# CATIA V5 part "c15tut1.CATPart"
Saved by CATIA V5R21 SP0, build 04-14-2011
Part number: Part1
Bounding box of the stored display mesh (mm): x -21 to 122, y 0 to 45, z -43 to 1
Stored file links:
  D:\CATIA V5R21 E-RESOURCES\CATIA-V5R21\catia-v5r21-prt\c15-catia-v5r20-prt\c15-catia-v5r21-tut01.CATPart
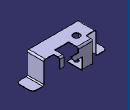
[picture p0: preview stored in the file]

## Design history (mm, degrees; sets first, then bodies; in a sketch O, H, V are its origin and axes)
SheetMetalParameters1: Thickness 1, BendRadius 2, KFactor 0.400515 {= log(min(100,max(20*SheetMetalParameters1.BendRadius,SheetMetalParameters1.Thickness)/SheetMetalParameters1.Thickness))/log(100)/2}, ReliefRadialLength 1, ReliefAxialLength 2, MinimumBendRadius 0
Body1 (main body)
  Sketch1 on xy-plane, origin (0, 0, 0), H (1, 0, 0), V (0, 1, 0)
    line L1 (0, 0) -> (101, 0)
    line L2 (101, 0) -> (101, 32)
    line L3 (101, 32) -> (82, 32)
    line L4 (82, 32) -> (82, 44)
    line L5 (82, 44) -> (74, 44)
    line L6 (74, 44) -> (74, 26)
    line L7 (74, 26) -> (47, 26)
    line L8 (47, 26) -> (47, 44)
    point P8 (47, 44)
    line L9 (47, 44) -> (20, 44)
    line L10 (20, 44) -> (20, 32)
    point P10 (20, 32)
    line L11 (20, 32) -> (0, 32)
    point P11 (0, 32)
    line L12 (0, 32) -> (0, 0)
    length L1 = 101
    length L2 = 32
    length L3 = 19
    length L5 = 8
    distance L1 L5 = 44
    distance L7 L1 = 26
    length L11 = 20
    length L9 = 27
    horizontal: L1 H, L3 H, L5 H, L7 H, L9 H, L11 H
    vertical: L2 V, L4 V, L6 V, L8 V, L10 V, L12 V
    coincidence: P8 L5, P10 L3, P11 V
  Wall1: Thickness 1, Profile Sketch1
  Flange1: Angle 90, Length 44, Radius 2, KFacteur 0.400515 {= log(min(100,max(20*Flange1.Radius,SheetMetalParameters1.Thickness)/SheetMetalParameters1.Thickness))/log(100)/2}, Guide edge [face of Wall1 | face of Wall1]
  Flange2: Angle 90, Length 44, Radius 2, KFacteur 0.400515 {= log(min(100,max(20*Flange2.Radius,SheetMetalParameters1.Thickness)/SheetMetalParameters1.Thickness))/log(100)/2}, Guide edge [face of Wall1 | face of Wall1]
  Flange3: Angle 90, Length 22, Radius 2, KFacteur 0.400515 {= log(min(100,max(20*Flange3.Radius,SheetMetalParameters1.Thickness)/SheetMetalParameters1.Thickness))/log(100)/2}, Guide edge [face of Flange2 | face of Flange2]
  Flange4: Angle 90, Length 22, Radius 2, KFacteur 0.400515 {= log(min(100,max(20*Flange4.Radius,SheetMetalParameters1.Thickness)/SheetMetalParameters1.Thickness))/log(100)/2}, Guide edge [face of Flange1 | face of Flange1]
  Sketch2 on face of Wall1, origin (47, 44, 0), H (-1, 0, 0), V (0, 0, 1)
    point P1 (0, 1)
    line L1 (0, 1) -> (0, -8)
    line L2 (0, -8) -> (-13, -8)
    line L3 (-13, -8) -> (-13, -18)
    line L4 (-13, -18) -> (8, -18)
    line L5 (8, -18) -> (8, -42)
    line L6 (8, -42) -> (27, -42)
    line L7 (27, -42) -> (27, 1)
    line L8 (27, 1) -> (0, 1)
    reference projected line E1 (27, 0) -> (27, 1) from edge [face of Wall1 | face of Wall1]
    reference projected line E2 (0, 1) -> (27, 1) from edge [face of Wall1 | face of Wall1]
    length L6 = 19
    length L7 = 43
    length L3 = 10
    distance L4 L8 = 19
    distance L3 L7 = 40
    coincidence: P1 V, L7 E1, L8 E2
    horizontal: L2 H, L4 H, L6 H
    vertical: L3 V, L5 V, L7 V, L1 V
  d_NewWallOnEdge1: NewWallOnEdge_Edge edge [face of Wall1 | face of Wall1], NewWallOnEdge_WallProfile Sketch2, NewWallOnEdge_Length 27, NewWallOnEdge_HeightLimitOffset 0, NewWallOnEdge_WidthOffset1 0, NewWallOnEdge_WidthOffset2 0, NewWallOnEdge_Angle 0, NewWallOnEdge_BendRadiusValue 2 {= SheetMetalParameters1.BendRadius}, NewWallOnEdge_BendTable SheetMetalParameters1, KFacteur 0.400515 {= log(min(100,max(20*d_NewWallOnEdge1.Radius,SheetMetalParameters1.Thickness)/SheetMetalParameters1.Thickness))/log(100)/2}
  Flange5: Angle 90, Length 19, Radius 2, KFacteur 0.400515 {= log(min(100,max(20*Flange5.Radius,SheetMetalParameters1.Thickness)/SheetMetalParameters1.Thickness))/log(100)/2}, Guide edge [face of Wall1 | face of Wall1]
  Flange6: Angle 90, Length 30, Radius 2, KFacteur 0.400515 {= log(min(100,max(20*Flange6.Radius,SheetMetalParameters1.Thickness)/SheetMetalParameters1.Thickness))/log(100)/2}, Guide edge [face of d_NewWallOnEdge1 | face of d_NewWallOnEdge1]
  Sketch3 on face of Wall1, origin (29.3791, 35.4737, 1), H (1, 0, 0), V (0, 1, 0)
    point P1 (-0.3791, -12.4737)
    reference projected line E1 (30.6209, 9.5263) -> (17.6209, 9.5263) from edge [face of d_NewWallOnEdge1 | face of d_NewWallOnEdge1]
    reference projected line E2 (-9.3791, 8.5263) -> (-9.3791, -3.4737) from edge [face of Wall1 | face of Wall1]
    distance P1 E1 = 22
    distance E2 P1 = 9
  Hole1: placed by Sketch3, at (29, 23, 1) direction (0, 0, -1), diameter 13, through (limit type 6)
  Sketch4 on face of Flange6, origin (31.6177, 25.4906, -41), H (1, 0, 0), V (0, 1, 0)
    point P1 (-2.6177, -2.4906)
    reference projected circle E1 centre (-2.6177, -2.4906) radius 6.5 from edge [face of Wall1 | face of Hole1]
    concentricity: P1 E1
  Hole2: placed by Sketch4, at (29, 23, -41) direction (0, 0, -1), diameter 8, through (limit type 6)
  Corner1: CornerChamferEdges (edge [face of Flange3 | face of Flange3]; edge [face of Flange3 | face of Flange3]; edge [face of Flange4 | face of Flange4]; edge [face of Flange4 | face of Flange4]), CornerRadius 7
  Corner2: CornerChamferEdges (edge [face of Wall1 | face of Wall1]; edge [face of Wall1 | face of Wall1]; edge [face of d_NewWallOnEdge1 | face of d_NewWallOnEdge1]; edge [face of Wall1 | face of Wall1]; edge [face of d_NewWallOnEdge1 | face of d_NewWallOnEdge1]; edge [face of Wall1 | face of Wall1]), CornerRadius 2
  Chamfer1: CornerChamferEdges edge [face of d_NewWallOnEdge1 | face of d_NewWallOnEdge1], ChamferAngle 45, ChamferLength1 6, ChamferLength2 0.5, ChamferPropagation 1, ChamferReverse false, ChamferType 1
